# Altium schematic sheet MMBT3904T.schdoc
size 127 x 101 mm
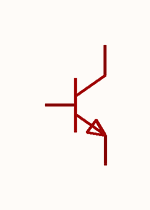
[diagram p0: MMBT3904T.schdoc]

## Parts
Q?  mmbt3904t_c61616  [SOT-523-3_L1.6-W0.8-P1.00-LS1.6-BR]  (value not drawn)

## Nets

Not connected (* = marked no-connect by the designer): Q? 1(B) 2(E) 3(C)

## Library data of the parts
Q? = mmbt3904t_c61616: 晶体管类型:NPN;集电极电流(Ic):200mA;集射极击穿电压(Vceo):40V;耗散功率(Pd):150mW;直流电流增益(hFE):300;; Manufacturer: CJ(江苏长电/长晶); AddInBom: yes; ModelId: 3e7fadd59d8d474faa89c2c7e0676879; ModelName: SOT-523-3P_L1.6-W0.8-H0.9-LS1.6-P0.50; ModelTransform: 63.48633,62.992,0,180,0,0,0,0,0; type: NPN; Current - Collector(Ic): 200mA; Collector - Emitter Voltage VCEO: 40V; Pd - Power Dissipation: 150mW; DC Current Gain: 300; Transition frequency(fT): 300MHz; Current - Collector Cutoff: 50nA; Vce Saturation(VCE(sat)): 300mV; Emitter-Base Voltage(Vebo): 6V; Number: 1个NPN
